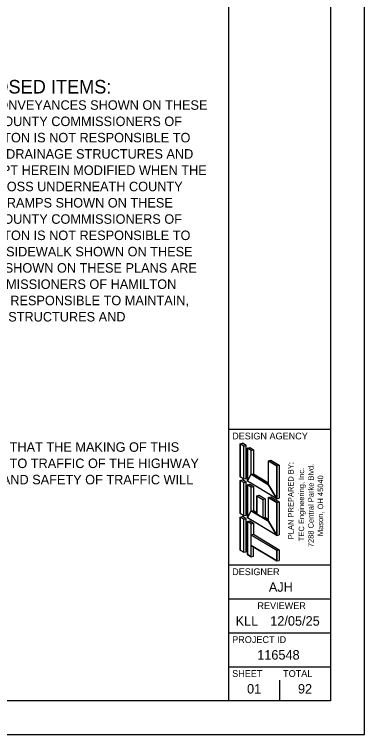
# Model space of a CAD drawing. Extents: x 0 to 34, y 0 to 22.
# Drawn here: x 28.84 to 34, y 0 to 10.61 of the extents above; entities that cross this region are included whole.
import ezdxf

# ---------------------------------------------------------------- set-up
doc = ezdxf.new("R2010")
doc.units = 0
for name, color, linetype in [('Default', 7, 'Continuous'), ('SH_Border', 7, 'Continuous'), ('SH_Cut_Line', 7, 'Continuous'), ('SH_Data', 7, 'Continuous'), ('SH_Text', 7, 'Continuous')]:
    doc.layers.add(name, color=color, linetype=linetype)

msp = doc.modelspace()

# ---------------------------------------------------------------- linework, layer by layer
at = {"layer": 'SH_Border'}
for p, q in [((32, 0.5), (32, 21.5)), ((32, 4.5), (33.5, 4.5)), ((32, 2.5), (33.5, 2.5)), ((32, 2), (33.5, 2)), ((32, 1.5), (33.5, 1.5)), ((32, 1), (33.5, 1))]:
    msp.add_line(p, q, dxfattribs=at)
msp.add_lwpolyline([(1.5, 21.5), (33.5, 21.5), (33.5, 0.5), (1.5, 0.5)], close=True, dxfattribs=at)
at = {"layer": 'SH_Cut_Line'}
msp.add_lwpolyline([(0, 0), (34, 0), (34, 22), (0, 22)], close=True, dxfattribs=at)
at = {"layer": 'SH_Data'}
for p, q in [((32.75, 3.5), (32.75, 3.5)), ((32.75, 0.5), (32.75, 0.8)), ((32.375, 0.675), (32.375, 0.675))]:
    msp.add_line(p, q, dxfattribs=at)
at = {"layer": 'SH_Text'}
for p, q in [((32.169, 4.285), (32.201, 4.294)), ((32.169, 3.799), (32.169, 4.285)), ((32.223, 4.253), (32.169, 4.285)), ((32.255, 4.261), (32.201, 4.294)), ((32.223, 4.253), (32.255, 4.261)), ((32.223, 3.767), (32.223, 4.253)), ((32.255, 3.775), (32.255, 4.261)), ((32.277, 4.221), (32.309, 4.229)), ((32.331, 4.188), (32.277, 4.221)), ((32.277, 3.735), (32.277, 4.221)), ((32.309, 4.229), (32.363, 4.196)), ((32.331, 4.188), (32.363, 4.196)), ((32.331, 3.837), (32.331, 4.188)), ((32.363, 4.196), (32.363, 3.845)), ((32.587, 4.034), (32.62, 4.042)), ((32.587, 3.683), (32.587, 4.034)), ((32.709, 3.961), (32.587, 4.034)), ((32.62, 4.042), (32.741, 3.97)), ((32.709, 3.961), (32.741, 3.97)), ((32.709, 3.475), (32.709, 3.961)), ((32.741, 3.97), (32.741, 3.484)), ((32.331, 3.837), (32.363, 3.845)), ((32.587, 3.683), (32.331, 3.837)), ((32.363, 3.845), (32.587, 3.711)), ((32.223, 3.767), (32.169, 3.799)), ((32.169, 3.745), (32.201, 3.754)), ((32.169, 3.259), (32.169, 3.745)), ((32.223, 3.713), (32.169, 3.745)), ((32.255, 3.722), (32.201, 3.754)), ((32.223, 3.767), (32.255, 3.775)), ((32.223, 3.713), (32.255, 3.722)), ((32.255, 3.236), (32.255, 3.722)), ((32.709, 3.475), (32.277, 3.735)), ((32.223, 3.227), (32.223, 3.713)), ((32.277, 3.681), (32.309, 3.689)), ((32.277, 3.195), (32.277, 3.681)), ((32.331, 3.648), (32.277, 3.681)), ((32.309, 3.689), (32.363, 3.656)), ((32.331, 3.648), (32.363, 3.656)), ((32.331, 3.297), (32.331, 3.648)), ((32.363, 3.656), (32.363, 3.305)), ((32.415, 3.519), (32.448, 3.527)), ((32.415, 3.519), (32.415, 3.247)), ((32.415, 3.519), (32.503, 3.466)), ((32.448, 3.527), (32.535, 3.474)), ((32.503, 3.466), (32.535, 3.474)), ((32.503, 3.466), (32.503, 3.194)), ((32.535, 3.474), (32.535, 3.202)), ((32.587, 3.494), (32.62, 3.502)), ((32.587, 3.143), (32.587, 3.494)), ((32.709, 3.421), (32.587, 3.494)), ((32.62, 3.502), (32.741, 3.43)), ((32.709, 3.475), (32.741, 3.484)), ((32.709, 3.421), (32.741, 3.43)), ((32.709, 2.935), (32.709, 3.421)), ((32.741, 3.43), (32.741, 2.944)), ((32.331, 3.297), (32.363, 3.305)), ((32.415, 3.247), (32.331, 3.297)), ((32.363, 3.305), (32.415, 3.274)), ((32.223, 3.227), (32.169, 3.259)), ((32.169, 3.205), (32.201, 3.215)), ((32.169, 2.719), (32.169, 3.205)), ((32.223, 3.173), (32.169, 3.205)), ((32.255, 3.181), (32.201, 3.215)), ((32.223, 3.227), (32.255, 3.236)), ((32.709, 2.935), (32.277, 3.195)), ((32.503, 3.194), (32.535, 3.202)), ((32.587, 3.143), (32.503, 3.194)), ((32.535, 3.202), (32.587, 3.171)), ((32.222, 3.173), (32.255, 3.181)), ((32.223, 2.687), (32.223, 3.173)), ((32.255, 2.695), (32.255, 3.181)), ((32.277, 3.141), (32.309, 3.151)), ((32.331, 3.108), (32.277, 3.141)), ((32.277, 2.655), (32.277, 3.141)), ((32.309, 3.151), (32.363, 3.116)), ((32.331, 3.108), (32.363, 3.116)), ((32.331, 2.944), (32.331, 3.108)), ((32.363, 3.116), (32.363, 2.952)), ((32.331, 2.944), (32.363, 2.952)), ((32.331, 2.944), (32.709, 2.717)), ((32.363, 2.952), (32.741, 2.725)), ((32.709, 2.935), (32.741, 2.944)), ((32.331, 2.787), (32.709, 2.56)), ((32.331, 2.622), (32.331, 2.787)), ((32.363, 2.63), (32.363, 2.767)), ((32.223, 2.687), (32.169, 2.719)), ((32.223, 2.687), (32.255, 2.695)), ((32.331, 2.622), (32.277, 2.655)), ((32.709, 2.717), (32.741, 2.725)), ((32.709, 2.56), (32.709, 2.717)), ((32.741, 2.725), (32.741, 2.568)), ((32.331, 2.622), (32.363, 2.63)), ((32.709, 2.56), (32.741, 2.568))]:
    msp.add_line(p, q, dxfattribs=at)
for points in [[(32.169, 3.799), (32.223, 3.767), (32.223, 4.253), (32.169, 4.285)], [(32.277, 3.735), (32.331, 3.837), (32.331, 4.188), (32.277, 4.221)], [(32.709, 3.475), (32.587, 3.683), (32.587, 4.034), (32.709, 3.961)], [(32.277, 3.735), (32.331, 3.837), (32.587, 3.683), (32.709, 3.475)], [(32.169, 3.259), (32.223, 3.227), (32.223, 3.713), (32.169, 3.745)], [(32.277, 3.195), (32.331, 3.297), (32.331, 3.648), (32.277, 3.681)], [(32.415, 3.247), (32.415, 3.519), (32.503, 3.466), (32.503, 3.194)], [(32.709, 2.935), (32.587, 3.143), (32.587, 3.494), (32.709, 3.421)], [(32.277, 3.195), (32.331, 3.297), (32.587, 3.143), (32.709, 2.935)], [(32.169, 2.719), (32.223, 2.687), (32.223, 3.173), (32.169, 3.205)], [(32.277, 2.655), (32.331, 2.622), (32.331, 3.108), (32.277, 3.141)], [(32.331, 2.787), (32.331, 2.944), (32.709, 2.717), (32.709, 2.56)]]:
    msp.add_lwpolyline(points, close=True, dxfattribs=at)

# ---------------------------------------------------------------- texts
at = {"layer": 'Default'}
for s, height, p in [('FUTURE MAINTENANCE OF PROPOSED ITEMS:', 0.2, (24.165, 9.448)), ('ALL PROPOSED DRAINAGE STRUCTURES AND CONVEYANCES SHOWN ON THESE ', 0.14, (24.165, 9.208)), ('PLANS ARE NOT ACCEPTED BY THE BOARD OF COUNTY COMMISSIONERS OF ', 0.14, (24.165, 8.968)), ('HAMILTON COUNTY, AND THE COUNTY OF HAMILTON IS NOT RESPONSIBLE TO ', 0.14, (24.165, 8.728)), ('MAINTAIN, REPAIR OR REPLACE ANY PROPOSED DRAINAGE STRUCTURES AND ', 0.14, (24.165, 8.488)), ('CONVEYANCES SHOWN ON THESE PLANS. EXCEPT HEREIN MODIFIED WHEN THE ', 0.14, (24.165, 8.248)), ('DRAINAGE STRUCTURES AND CONVEYANCES CROSS UNDERNEATH COUNTY ', 0.14, (24.165, 8.008)), ('ROADWAY.ALL PROPOSED SIDEWALK AND CURB RAMPS SHOWN ON THESE ', 0.14, (24.165, 7.768)), ('PLANS ARE NOT ACCEPTED BY THE BOARD OF COUNTY COMMISSIONERS OF ', 0.14, (24.165, 7.528)), ('HAMILTON COUNTY, AND THE COUNTY OF HAMILTON IS NOT RESPONSIBLE TO ', 0.14, (24.165, 7.288)), ('MAINTAIN, REPAIR OR REPLACE ANY PROPOSED SIDEWALK SHOWN ON THESE ', 0.14, (24.165, 7.048)), ('PLANS. ALL PROPOSED CURB AND CURB INLETS SHOWN ON THESE PLANS ARE ', 0.14, (24.165, 6.808)), ('NOT ACCEPTED BY THE BOARD OF COUNTY COMMISSIONERS OF HAMILTON ', 0.14, (24.165, 6.568)), ('COUNTY, AND THE COUNTY OF HAMILTON IS NOT RESPONSIBLE TO MAINTAIN, ', 0.14, (24.165, 6.328)), ('REPAIR OR REPLACE ANY PROPOSED DRAINAGE STRUCTURES AND ', 0.14, (24.165, 6.088)), ('I HEREBY APPROVE THESE PLANS AND DECLARE THAT THE MAKING OF THIS ', 0.14, (24.165, 4.168)), ('IMPROVEMENT WILL NOT REQUIRE THE CLOSING TO TRAFFIC OF THE HIGHWAY ', 0.14, (24.165, 3.928)), ('AND THAT PROVISIONS FOR THE MAINTENANCE AND SAFETY OF TRAFFIC WILL ', 0.14, (24.165, 3.688))]:
    msp.add_text(s, height=height, dxfattribs=at).set_placement(p)
for s, p in [('PLAN PREPARED BY:', (32.954, 2.88)), ('7288 Central Parke Blvd.', (33.25, 2.762)), ('TEC Engineering, Inc.', (33.11, 2.851)), ('Mason, OH 45040', (33.39, 2.925))]:
    msp.add_text(s, height=0.08, rotation=90, dxfattribs=at).set_placement(p)
at = {"layer": 'SH_Data'}
for s, height, p in [('DESIGN AGENCY', 0.1, (32.05, 4.35)), ('DESIGNER', 0.1, (32.05, 2.35)), ('AJH', 0.14, (32.59, 2.105)), ('REVIEWER', 0.1, (32.422, 1.85)), ('KLL', 0.14, (32.101, 1.605)), ('12/05/25', 0.14, (32.611, 1.605)), ('PROJECT ID', 0.1, (32.05, 1.35)), ('116548', 0.14, (32.419, 1.105)), ('SHEET', 0.1, (32.05, 0.85)), ('TOTAL', 0.1, (32.8, 0.85)), ('01', 0.14, (32.269, 0.605)), ('92', 0.14, (33.019, 0.605))]:
    msp.add_text(s, height=height, dxfattribs=at).set_placement(p)

doc.saveas('drawing.dxf')
